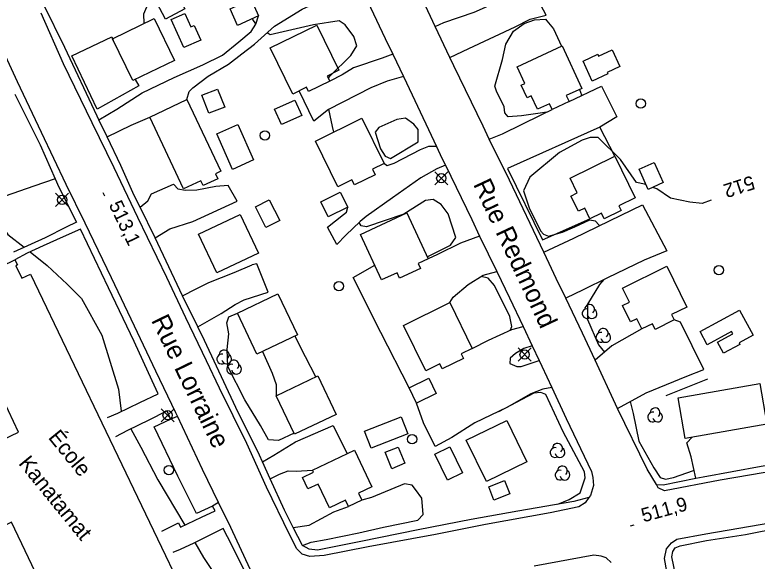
# Model space of a CAD drawing. Extents: x 347312 to 350503, y 6073086 to 6076432.
# Drawn here: x 348862.1 to 349021.2, y 6074615.9 to 6074732.9 of the extents above; entities that cross this region are included whole.
import ezdxf

# ---------------------------------------------------------------- set-up
doc = ezdxf.new("R2010")
doc.units = 0
for name, color, linetype in [('Level 19', 7, 'Continuous'), ('Level 2', 7, 'Continuous'), ('Level 21', 7, 'Continuous'), ('Level 22', 7, 'Continuous'), ('Level 3', 7, 'Continuous'), ('Level 31', 7, 'Continuous'), ('Level 36', 7, 'Continuous'), ('Level 37', 7, 'Continuous'), ('Level 44', 7, 'Continuous')]:
    doc.layers.add(name, color=color, linetype=linetype)

msp = doc.modelspace()

# ---------------------------------------------------------------- linework, layer by layer
at = {"layer": 'Level 19'}
for points in [[(348889.87, 6074731.09), (348889.77, 6074733.14), (348891.41, 6074737.04), (348894.53, 6074740.4), (348897.34, 6074743), (348900.6, 6074744.53), (348903.28, 6074745.57), (348908.05, 6074747.46), (348909.47, 6074746.18)], [(348955.36, 6074723.79), (348955.36, 6074723.79), (348959.47, 6074725.71), (348969.36, 6074730.33), (348972.59, 6074731.98), (348976, 6074732.88), (348974.22, 6074736.25), (348972.65, 6074740.46)], [(348898.99, 6074714.8), (348899.51, 6074716.53), (348900.28, 6074717.32), (348903.57, 6074719.8), (348907.9, 6074722.38), (348910.8, 6074724.6), (348913.53, 6074726.67), (348917.76, 6074730.47), (348923.75, 6074734.15), (348929.07, 6074736.65), (348933.78, 6074738.8), (348935.83, 6074739.83)], [(348952.23, 6074730.46), (348954.07, 6074731.26), (348960.6, 6074733.49), (348966.05, 6074735.9)], [(348880.12, 6074710.46), (348884.02, 6074712.69), (348889.45, 6074716.21), (348896.27, 6074719.53), (348902.39, 6074722.25), (348906.63, 6074724.31), (348910.16, 6074727.13), (348912.78, 6074729.33), (348913.78, 6074730.94), (348914.38, 6074732.74)], [(348943.13, 6074724.49), (348940.83, 6074723.62), (348934.69, 6074721.56), (348932.3, 6074720.08), (348929.65, 6074718.75)], [(348945.43, 6074719.71), (348941.95, 6074718.7), (348938.42, 6074717.32), (348929.38, 6074712.67), (348926.25, 6074710.18), (348923.1, 6074716.64)], [(348980.97, 6074714.37), (348987.91, 6074717.63), (348991.14, 6074711.08), (348987.53, 6074708.87)], [(348963.83, 6074706.32), (348966.68, 6074707.43), (348974.97, 6074711.53), (348977.28, 6074712.65)], [(348881.9, 6074706.76), (348887.09, 6074709.31), (348891.03, 6074711.03)], [(348952.52, 6074704.73), (348950.76, 6074704.69), (348948.98, 6074704.02), (348943.34, 6074701.09), (348941.86, 6074700.57), (348941.28, 6074701.05)], [(348954.42, 6074700.74), (348952.58, 6074699.94), (348949.13, 6074698.01), (348943.09, 6074693.76), (348937.45, 6074689.76), (348936.16, 6074688.68), (348933.07, 6074685.7), (348931.18, 6074683.72), (348929.11, 6074687.45), (348932.55, 6074690.19), (348933.24, 6074690.63), (348933.47, 6074691.72)], [(348870.76, 6074697.79), (348866.2, 6074696.26), (348860.06, 6074694.06), (348857.85, 6074693.33)], [(348888.99, 6074691.71), (348890.6, 6074693.07), (348891.39, 6074694.56), (348896.12, 6074696.63)], [(348892.24, 6074685.13), (348895.33, 6074687.08), (348900.27, 6074688.67), (348909.76, 6074693.02), (348907.83, 6074696.4), (348905.18, 6074696.14), (348901.16, 6074695.34), (348898.61, 6074695.32), (348897.15, 6074695.61), (348896.12, 6074696.63)], [(348975.48, 6074682.12), (348981.91, 6074685.1), (348992.11, 6074690.05), (348996.65, 6074692.21), (349001.89, 6074682.35), (348997.04, 6074680.39), (348989.16, 6074676.63), (348983.93, 6074674.05), (348980.21, 6074672.26)], [(348961.76, 6074685.55), (348957.64, 6074683.99), (348952.75, 6074681.62), (348950.72, 6074680.67)], [(348898.07, 6074672.74), (348900.99, 6074674.24), (348903.73, 6074675.57), (348909.15, 6074677.71), (348913.03, 6074679.39)], [(348901.32, 6074666.13), (348906.35, 6074668.96), (348909.38, 6074670.91), (348911.31, 6074671.86), (348916.46, 6074673.54), (348913.97, 6074679.57), (348913.03, 6074679.39)], [(348946.65, 6074653.02), (348940.58, 6074664.91), (348934.66, 6074676.64), (348939.29, 6074679.29)], [(348955.36, 6074671.28), (348956.11, 6074672.45), (348959.26, 6074675.18), (348962.51, 6074677.16), (348965.43, 6074677.96)], [(348991.31, 6074648.63), (348997.42, 6074651.96), (349006.19, 6074655.56), (349009.84, 6074656.97), (349004.8, 6074667.12), (349003.47, 6074667.58)], [(348960.18, 6074661.47), (348963.66, 6074663.26), (348968.62, 6074665.55), (348971.06, 6074666.19)], [(348996.55, 6074665.65), (348990.08, 6074662.02), (348986.51, 6074658.95)], [(348973.02, 6074662.03), (348971.21, 6074661.49), (348969.43, 6074660.37), (348968.28, 6074659.4), (348968.26, 6074658.25), (348969.73, 6074657.59), (348970.63, 6074657.59), (348974.49, 6074658.91)], [(348977.21, 6074653.13), (348975.32, 6074652.74), (348972.76, 6074651.72), (348967.55, 6074648.85), (348960.76, 6074645.53), (348955.82, 6074642.42), (348952.2, 6074640.44), (348949.75, 6074645.51), (348948.24, 6074649.74)], [(348905.8, 6074628.47), (348904.52, 6074627.66), (348901.07, 6074626.12), (348897.09, 6074634.13), (348891.98, 6074644.69), (348895.49, 6074646.35), (348896.99, 6074646.94)], [(348915.23, 6074637.18), (348917.61, 6074638.62), (348922.27, 6074641.47), (348930.37, 6074644.95), (348933.35, 6074638.92)], [(349008.08, 6074633.66), (349007.08, 6074638.27), (349006.14, 6074641.28), (349007.31, 6074642.44)], [(348916.87, 6074633.55), (348918.87, 6074634.55), (348920.74, 6074635.29), (348922.41, 6074635.22), (348925.92, 6074635.39)], [(348923.79, 6074619.23), (348925.63, 6074619.98), (348928.87, 6074620.52), (348935.89, 6074621.96), (348941.18, 6074623.16), (348948.49, 6074624.7), (348949.62, 6074625.87), (348949.38, 6074629.39), (348948.02, 6074631.27), (348947.28, 6074632.16), (348945.66, 6074632.47), (348938.55, 6074629.51), (348936.47, 6074628.98)], [(348921.8, 6074623.13), (348925.21, 6074623.65), (348930.49, 6074626.44), (348933.64, 6074627.64)]]:
    msp.add_lwpolyline(points, dxfattribs=at)
at = {"layer": 'Level 2'}
for points in [[(348913.79, 6074730.97), (348913.12, 6074731.93), (348913.06, 6074732.14)], [(348965.02, 6074717.62), (348966.66, 6074723.33), (348967.35, 6074726.66), (348968.98, 6074729.4), (348971.3, 6074731.05), (348973.51, 6074731.85), (348975.9, 6074731.97), (348976.17, 6074731.65), (348977.59, 6074729.96), (348979.28, 6074726.22)], [(348929.35, 6074719.34), (348929.67, 6074719.78), (348934.17, 6074724.25), (348935.41, 6074726.29), (348934.76, 6074728.32), (348932.91, 6074730.8), (348931.62, 6074731.61), (348926.16, 6074730.82), (348916.88, 6074728.62), (348916.19, 6074729.06)], [(348976.14, 6074712.1), (348974.23, 6074711.78), (348970.7, 6074711.31), (348967.84, 6074711.11), (348967.17, 6074711.91), (348967.04, 6074713.24), (348965.38, 6074716.56), (348965.02, 6074717.62)], [(348983.15, 6074716.94), (348983.58, 6074715.78), (348983.52, 6074715.57)], [(348930.53, 6074707.83), (348930.25, 6074709), (348929.75, 6074711.4), (348929.44, 6074712.7)], [(348942.65, 6074702.19), (348948.55, 6074705.71), (348948.57, 6074708.39), (348947.68, 6074709.54), (348945.89, 6074710.77), (348943.97, 6074710.53), (348940.16, 6074708.76), (348939.34, 6074707.76), (348940.48, 6074704.24), (348941.54, 6074702.62), (348942.65, 6074702.19)], [(348997.43, 6074696.52), (348997.1, 6074696.65), (348995.36, 6074697), (348991.92, 6074701.92), (348987.14, 6074706.63), (348985.46, 6074706.66), (348983.76, 6074706.06), (348978.85, 6074703.45), (348972.48, 6074698.15), (348971.16, 6074695.22), (348972.38, 6074691.61), (348974.79, 6074686.66), (348975.44, 6074685.98), (348976.51, 6074685.52), (348979.54, 6074686.4), (348982.18, 6074687.49), (348985.35, 6074689.03), (348986.53, 6074688.8), (348987.36, 6074687.9), (348987.46, 6074687.79)], [(349011.37, 6074693.26), (349009.45, 6074692.55), (349006.8, 6074692.82), (349002.69, 6074693.68), (348999.77, 6074695.63), (348998.87, 6074695.97)], [(348950.54, 6074681.06), (348955.5, 6074683.62), (348956.66, 6074685.2), (348955.04, 6074690.29), (348953.52, 6074692.28), (348951.8, 6074693.34), (348950.18, 6074693.19), (348945.49, 6074690.22), (348937.49, 6074687.51), (348936.39, 6074687.73), (348935.92, 6074688.45)], [(348857.03, 6074691.92), (348857.56, 6074690.83), (348858.72, 6074688.72), (348860.64, 6074685.9), (348864.14, 6074683.13)], [(348865.39, 6074682.14), (348869.06, 6074679.23), (348873.36, 6074675.24), (348876.43, 6074672.2), (348880.74, 6074664.29), (348884.36, 6074652.72), (348884.93, 6074648.04), (348884.95, 6074648.01)], [(348968.37, 6074665.43), (348968.66, 6074666.15), (348968.22, 6074668.29), (348964.96, 6074674.96), (348963.57, 6074676.52), (348962.05, 6074676.88)], [(348988.37, 6074676.24), (348987.46, 6074675.16), (348984.85, 6074670.99), (348984.85, 6074667.65), (348987.23, 6074662.21), (348988.55, 6074660.7)], [(348921.97, 6074643.31), (348918.64, 6074641.72), (348916.53, 6074641.92), (348914.76, 6074644.98), (348911.42, 6074650.49), (348907.81, 6074657.6), (348907.64, 6074661.25), (348908.03, 6074664.61), (348907.58, 6074666.96), (348908.02, 6074668.24), (348909.83, 6074669)], [(348915.24, 6074660.85), (348917.27, 6074656.2), (348918.11, 6074653.72), (348918.14, 6074651.35)], [(348978.55, 6074628.12), (348980.96, 6074629.09), (348983.3, 6074630.54), (348984.39, 6074633.73), (348984.21, 6074635.02), (348979.65, 6074643.61), (348975.97, 6074651.59), (348974.9, 6074652.05), (348973.36, 6074651.9), (348965.79, 6074647.87), (348965.75, 6074647.97)], [(348994.05, 6074650.12), (348994.69, 6074647.56), (348995.91, 6074641.61), (348999.12, 6074635.9), (349000.46, 6074633.85)], [(348886.98, 6074644.26), (348889.1, 6074640.34), (348892.77, 6074633.35), (348898.55, 6074623.6)], [(349000.46, 6074633.85), (349001.58, 6074633.5), (349003.33, 6074633.84), (349007.61, 6074635.32), (349007.71, 6074635.34)], [(348900.73, 6074619.88), (348902.59, 6074616.7), (348907.52, 6074609.27), (348908.57, 6074606.82), (348908.49, 6074603.65), (348907.56, 6074596.51), (348907.55, 6074596.27)]]:
    msp.add_lwpolyline(points, dxfattribs=at)
at = {"layer": 'Level 21'}
for points in [[(348976.64, 6074679.7), (348975.48, 6074682.12), (348968.12, 6074697.51), (348963.83, 6074706.32), (348962.48, 6074709.1), (348956.2, 6074721.99), (348955.36, 6074723.79), (348952.23, 6074730.46), (348949.68, 6074735.9), (348944.97, 6074745.62), (348943.05, 6074749.58), (348942.14, 6074751.46), (348936.66, 6074762.79), (348935.57, 6074764.98), (348932.5, 6074771.18), (348931.17, 6074773.85), (348923.43, 6074790.67), (348914.53, 6074809.33), (348908.74, 6074821.47)], [(348935.83, 6074739.83), (348941.52, 6074727.84), (348943.13, 6074724.49), (348945.43, 6074719.71), (348947.3, 6074715.82), (348952.52, 6074704.73), (348953.68, 6074702.26), (348954.42, 6074700.74), (348960.06, 6074689.08), (348961.76, 6074685.55), (348965.43, 6074677.96), (348968.18, 6074672.29), (348971.06, 6074666.19), (348973.02, 6074662.03), (348974.49, 6074658.91), (348975.08, 6074657.68), (348977.21, 6074653.13), (348980.33, 6074646.47), (348985.73, 6074635.09), (348986.04, 6074633.83), (348986.18, 6074632.13), (348985.55, 6074630), (348985.18, 6074629.51)], [(348985.18, 6074629.51), (348984.38, 6074628.42), (348983, 6074627.55), (348976.85, 6074626.24), (348963, 6074623.75), (348952.31, 6074621.64), (348937.84, 6074619), (348928.44, 6074617.15), (348925.39, 6074616.92), (348923.74, 6074617.43), (348922.57, 6074618.56), (348920.98, 6074621.62), (348916.08, 6074631.75), (348911.86, 6074641.08), (348906.03, 6074652.94), (348903.2, 6074658.83), (348898.76, 6074668.06), (348894.71, 6074676.65), (348888.47, 6074689.55), (348883.4, 6074700.18), (348878.73, 6074709.78), (348872.58, 6074722.4), (348867.8, 6074733.25)], [(348912.56, 6074614.21), (348908.42, 6074623.14), (348905.8, 6074628.47), (348902.33, 6074635.52), (348896.99, 6074646.94), (348896.63, 6074647.71), (348892.32, 6074656.6), (348887.75, 6074666.26), (348882.85, 6074676.57), (348877.17, 6074688.27), (348873.14, 6074696.57), (348867.85, 6074707.71), (348862.67, 6074718.56), (348857.88, 6074728.75)], [(349028.79, 6074635.92), (349013.28, 6074633.25), (349001.35, 6074631), (349000.05, 6074631.65), (348999.63, 6074632.34), (348997.63, 6074635.61), (348991.31, 6074648.63), (348990.87, 6074649.57), (348986.51, 6074658.95), (348983.8, 6074664.77), (348980.21, 6074672.26), (348978.19, 6074676.48), (348976.64, 6074679.7)], [(349003.17, 6074606.57), (349001.4, 6074616.51), (349001.81, 6074618.53), (349002.87, 6074619.87), (349004, 6074620.6), (349010.22, 6074621.74), (349024.39, 6074624.2), (349034.18, 6074625.94), (349046.52, 6074628.23), (349057.62, 6074630.38), (349061.26, 6074630.64), (349061.26, 6074630.64), (349076.97, 6074633.95), (349079.05, 6074634.34), (349093.69, 6074637.13), (349111.47, 6074640.3), (349123.49, 6074642.7), (349133.45, 6074644.58)], [(348989.97, 6074615.59), (348988.9, 6074616.59), (348987.83, 6074616.97), (348986.2, 6074617.2), (348973.44, 6074614.86)]]:
    msp.add_lwpolyline(points, dxfattribs=at)
at = {"layer": 'Level 22'}
for points in [[(348985.18, 6074629.51), (348981.91, 6074628.7), (348969.91, 6074626.63), (348959.94, 6074624.83), (348948.59, 6074622.61), (348936.31, 6074620.15), (348927, 6074618.29), (348925.25, 6074618.49), (348923.79, 6074619.23), (348921.8, 6074623.13), (348919.91, 6074626.8), (348916.87, 6074633.55), (348915.23, 6074637.18), (348914.58, 6074638.61), (348909.53, 6074648.84), (348902.77, 6074663.17), (348901.32, 6074666.13), (348898.07, 6074672.74), (348897.47, 6074673.97), (348892.24, 6074685.13), (348888.99, 6074691.71), (348887.74, 6074694.26), (348884.86, 6074700.65), (348881.9, 6074706.76), (348880.12, 6074710.46), (348879.74, 6074711.24), (348872.82, 6074725.95), (348868.31, 6074735.09)], [(348862.1, 6074715.97), (348867.53, 6074705.11), (348870.76, 6074697.79), (348871.55, 6074696.02), (348875.38, 6074688.51), (348873.15, 6074687.45), (348868.6, 6074685.13), (348861.86, 6074682.11)], [(348999.63, 6074632.34), (349001.1, 6074632.29), (349008.08, 6074633.66), (349009.66, 6074633.97), (349022.09, 6074636.25), (349024.64, 6074636.66), (349030.29, 6074637.55), (349038.57, 6074639.3), (349042.69, 6074639.96), (349047.62, 6074641.01), (349056, 6074642.46), (349057.78, 6074643.58), (349058.26, 6074644.44), (349058.76, 6074645.92), (349058.81, 6074647.48), (349056.3, 6074655.06), (349053.4, 6074663.3), (349052.31, 6074666.09), (349051.25, 6074668.84), (349047.78, 6074677.17), (349047.54, 6074677.77), (349043.16, 6074686.6), (349038.83, 6074695.01), (349040.24, 6074695.56)], [(348881.96, 6074646.69), (348884.17, 6074647.64), (348888.91, 6074649.88), (348892.88, 6074651.78), (348891.55, 6074654.53), (348887.7, 6074662.98), (348882.2, 6074674.45), (348876.18, 6074687), (348872.47, 6074685.39), (348868.23, 6074683.42), (348864.77, 6074681.87), (348862.16, 6074680.43)], [(348883.8, 6074642.63), (348886.37, 6074643.96), (348890.9, 6074646.18), (348894.68, 6074648.14), (348895.49, 6074646.35)], [(349004.28, 6074610.3), (349002.92, 6074616.87), (349003.18, 6074618), (349003.65, 6074618.78), (349004.72, 6074619.22), (349010.35, 6074620.33), (349018.71, 6074621.62), (349034.24, 6074624.7), (349044.78, 6074626.53), (349057.42, 6074628.92), (349061.6, 6074629.33), (349062.52, 6074628.68), (349062.93, 6074627.2), (349064.58, 6074627.31)], [(348893.65, 6074622.34), (348897.2, 6074624.11), (348897.66, 6074623.18), (348902.11, 6074625.32), (348905.04, 6074626.66), (348904.52, 6074627.66)], [(348891.79, 6074597), (348897.96, 6074594.77), (348908.57, 6074596.43), (348916.04, 6074597.8), (348915.4, 6074602.02), (348914.05, 6074607.02), (348912.11, 6074612.28), (348908.62, 6074619.33), (348906.78, 6074622.93), (348900.48, 6074619.76), (348897.55, 6074618.42), (348896.01, 6074617.74)]]:
    msp.add_lwpolyline(points, dxfattribs=at)
at = {"layer": 'Level 3'}
for p, q in [((348881, 6074694.87), (348881.35, 6074694.15)), ((348994.08, 6074623.46), (348994.85, 6074623.68))]:
    msp.add_line(p, q, dxfattribs=at)
at = {"layer": 'Level 31'}
for points in [[(348892.55, 6074735.52), (348896.72, 6074737.75), (348898.6, 6074734.21), (348894.43, 6074731.98), (348892.55, 6074735.52)], [(348908.25, 6074734.18), (348912.78, 6074736.25), (348914.38, 6074732.74), (348909.85, 6074730.67), (348908.25, 6074734.18)], [(348891.99, 6074732.12), (348896.33, 6074723.18), (348887.4, 6074718.85), (348883.06, 6074727.79), (348891.99, 6074732.12)], [(348899.85, 6074730.33), (348900.59, 6074730.66), (348901.98, 6074727.53), (348898.35, 6074725.91), (348895.67, 6074731.93), (348898.57, 6074733.21), (348899.85, 6074730.33)], [(348929.65, 6074718.75), (348925.09, 6074716.52), (348924.66, 6074717.4), (348921.71, 6074715.96), (348916.88, 6074725.85), (348926.86, 6074730.72), (348931.59, 6074721.04), (348929.1, 6074719.82), (348929.65, 6074718.75)], [(348980.97, 6074714.37), (348977.28, 6074712.65), (348976.71, 6074713.87), (348974.16, 6074712.69), (348972.83, 6074715.55), (348971.92, 6074715.13), (348970.65, 6074717.86), (348971.45, 6074718.23), (348969.78, 6074721.82), (348979.44, 6074726.3), (348983.67, 6074717.18), (348980.3, 6074715.62), (348980.97, 6074714.37)], [(348985.89, 6074718.74), (348983.92, 6074722.99), (348987.08, 6074724.47), (348987.26, 6074724.08), (348990.16, 6074725.43), (348991.83, 6074721.83), (348989.1, 6074720.56), (348989.23, 6074720.29), (348985.89, 6074718.74)], [(348905.59, 6074717.03), (348907.11, 6074713.16), (348903.74, 6074711.83), (348902.22, 6074715.71), (348905.59, 6074717.03)], [(348906.26, 6074699.43), (348905.13, 6074698.89), (348905.64, 6074697.8), (348902.47, 6074696.36), (348901.97, 6074697.4), (348898.3, 6074695.66), (348891.03, 6074711.03), (348898.99, 6074714.8), (348906.26, 6074699.43)], [(348917.82, 6074712.71), (348922.14, 6074714.67), (348923.63, 6074711.4), (348919.32, 6074709.43), (348917.82, 6074712.71)], [(348931.35, 6074696.12), (348926.55, 6074705.87), (348936.5, 6074710.76), (348941.28, 6074701.05), (348938.82, 6074699.84), (348939.39, 6074698.67), (348934.94, 6074696.48), (348934.38, 6074697.61), (348931.35, 6074696.12)], [(348909.92, 6074709.46), (348913.3, 6074701.84), (348908.78, 6074699.83), (348905.4, 6074707.45), (348909.92, 6074709.46)], [(348992.12, 6074691.04), (348988.45, 6074689.25), (348987.86, 6074690.46), (348985.39, 6074689.25), (348984.28, 6074691.52), (348982.91, 6074690.85), (348981.32, 6074694.11), (348982.68, 6074694.78), (348981.13, 6074697.95), (348990.75, 6074702.65), (348995.11, 6074693.75), (348991.59, 6074692.02), (348992.12, 6074691.04)], [(348999.15, 6074701.32), (349001.12, 6074696.99), (348997.89, 6074695.52), (348995.92, 6074699.85), (348999.15, 6074701.32)], [(348933.47, 6074691.72), (348929.31, 6074689.66), (348927.71, 6074692.9), (348931.86, 6074694.96), (348933.47, 6074691.72)], [(348916.65, 6074693.32), (348918.9, 6074688.85), (348915.93, 6074687.36), (348913.68, 6074691.83), (348916.65, 6074693.32)], [(348910.39, 6074690.18), (348914.33, 6074681.9), (348905.4, 6074677.66), (348901.47, 6074685.93), (348910.39, 6074690.18)], [(348940.73, 6074676.15), (348936.23, 6074685.91), (348946.18, 6074690.51), (348950.72, 6074680.67), (348948.58, 6074679.68), (348949.08, 6074678.61), (348944.58, 6074676.54), (348944.05, 6074677.68), (348940.73, 6074676.15)], [(348848.4, 6074673.84), (348862.16, 6074680.43), (348862.67, 6074679.36), (348862.32, 6074679.19), (348863.61, 6074676.49), (348865.52, 6074677.41), (348899.47, 6074606.52)], [(349003.47, 6074667.58), (348999.39, 6074665.56), (348998.8, 6074666.76), (348996.55, 6074665.65), (348995.47, 6074667.84), (348994.08, 6074667.16), (348992.35, 6074670.65), (348993.85, 6074671.39), (348992.38, 6074674.37), (349001.89, 6074679.06), (349006.18, 6074670.34), (349002.88, 6074668.71), (349003.47, 6074667.58)], [(348918.51, 6074673.16), (348922.7, 6074664.42), (348914.01, 6074660.26), (348909.83, 6074669), (348918.51, 6074673.16)], [(348950.19, 6074656.65), (348945.4, 6074666.39), (348955.36, 6074671.28), (348960.18, 6074661.47), (348957.83, 6074660.31), (348958.32, 6074659.32), (348953.75, 6074657.07), (348953.22, 6074658.14), (348950.19, 6074656.65)], [(349017.48, 6074669.67), (349020.38, 6074664.32), (349017.38, 6074662.69), (349017.56, 6074662.35), (349014.03, 6074660.43), (349012.73, 6074662.82), (349015.99, 6074664.59), (349015.72, 6074665.07), (349010.54, 6074662.26), (349009.01, 6074665.07), (349017.48, 6074669.67)], [(348922.07, 6074643.08), (348918.14, 6074651.35), (348927.05, 6074655.59), (348930.98, 6074647.33), (348922.07, 6074643.08)], [(348950.88, 6074655.07), (348952.47, 6074651.79), (348948.24, 6074649.74), (348946.65, 6074653.02), (348950.88, 6074655.07)], [(349004.28, 6074650.87), (349021.79, 6074653.98), (349023.34, 6074645.28), (349005.82, 6074642.17), (349004.28, 6074650.87)], [(348854.23, 6074639.4), (348862.91, 6074643.55), (348858.54, 6074652.68)], [(348944.93, 6074646.8), (348946.35, 6074643.15), (348938.51, 6074640.1), (348937.09, 6074643.75), (348944.93, 6074646.8)], [(348967.61, 6074646.06), (348971.89, 6074637.19), (348963.19, 6074632.98), (348958.9, 6074641.85), (348967.61, 6074646.06)], [(348934.9, 6074639.66), (348938.62, 6074631.83), (348935.76, 6074630.47), (348936.47, 6074628.98), (348933.64, 6074627.64), (348933, 6074629), (348929.55, 6074627.36), (348927.14, 6074632.41), (348924.95, 6074631.37), (348923.78, 6074633.83), (348926.13, 6074634.95), (348925.92, 6074635.39), (348934.9, 6074639.66)], [(348944.28, 6074640.36), (348945.7, 6074636.87), (348942.9, 6074635.72), (348941.47, 6074639.22), (348944.28, 6074640.36)], [(348954.86, 6074633.29), (348952.17, 6074638.82), (348955.39, 6074640.38), (348958.08, 6074634.85), (348954.86, 6074633.29)], [(348968.21, 6074630.32), (348964.82, 6074628.97), (348963.69, 6074631.81), (348967.08, 6074633.16), (348968.21, 6074630.32)], [(348868.01, 6074610.47), (348861.41, 6074624.25), (348848.82, 6074618.22), (348849.4, 6074617), (348846.49, 6074615.61), (348845.84, 6074616.98), (348831.86, 6074610.28)]]:
    msp.add_lwpolyline(points, dxfattribs=at)
at = {"layer": 'Level 36'}
for p, q in [((348952.13, 6074696.51), (348954.95, 6074699.33)), ((348952.13, 6074699.33), (348954.95, 6074696.51)), ((348870.84, 6074691.89), (348873.66, 6074694.71)), ((348870.84, 6074694.71), (348873.66, 6074691.89)), ((348969.99, 6074658.76), (348972.81, 6074661.58)), ((348969.99, 6074661.58), (348972.81, 6074658.76)), ((348893.47, 6074645.75), (348896.29, 6074648.57)), ((348893.47, 6074648.57), (348896.29, 6074645.75))]:
    msp.add_line(p, q, dxfattribs=at)
for centre in [(348996.29, 6074713.93), (348915.72, 6074707.1), (348953.54, 6074697.92), (348872.25, 6074693.3), (349013.05, 6074678.24), (348931.58, 6074674.81), (348971.4, 6074660.17), (348894.88, 6074647.16), (348947.27, 6074642.03), (348895.15, 6074635.41)]:
    msp.add_circle(centre, 1, dxfattribs=at)
at = {"layer": 'Level 37'}
for points in [[(348887.9, 6074719.09), (348888.7, 6074717.72), (348879.77, 6074712.7), (348874.33, 6074724.18), (348882.89, 6074728.21), (348883.23, 6074727.43)], [(348990.75, 6074702.65), (348987.53, 6074708.87), (348967.71, 6074699.99), (348975.25, 6074684.7), (348985.39, 6074689.25)], [(348926.61, 6074655.38), (348924.43, 6074659.64), (348922.17, 6074664.16)], [(349001.75, 6074651.36), (349010.67, 6074654.94)]]:
    msp.add_lwpolyline(points, dxfattribs=at)
at = {"layer": 'Level 44'}
for centre, start, end in [((348984.8, 6074668.94), 76.8848, 299.5691), ((348985.32, 6074669.84), 314.0633, 179.7519), ((348985.85, 6074668.94), 192.2171, 59.6742), ((348988.25, 6074664.73), 314.0633, 179.7519), ((348987.73, 6074663.83), 76.8848, 299.5691), ((348988.78, 6074663.83), 192.2171, 59.6742), ((348907, 6074660.09), 314.0633, 179.7519), ((348906.48, 6074659.19), 76.8848, 299.5691), ((348907.53, 6074659.19), 192.2171, 59.6742), ((348909.11, 6074657.93), 314.0633, 179.7519), ((348908.59, 6074657.03), 76.8848, 299.5691), ((348909.64, 6074657.03), 192.2171, 59.6742), ((348998.85, 6074646.78), 76.8848, 299.5691), ((348999.37, 6074647.68), 314.0633, 179.7519), ((348999.9, 6074646.78), 192.2171, 59.6742), ((348977.93, 6074639.18), 76.8848, 299.5691), ((348978.45, 6074640.08), 314.0633, 179.7519), ((348978.98, 6074639.18), 192.2171, 59.6742), ((348978.99, 6074634.34), 76.8848, 299.5691), ((348979.51, 6074635.24), 314.0633, 179.7519), ((348980.04, 6074634.34), 192.2171, 59.6742)]:
    msp.add_arc(centre, 1.05, start, end, dxfattribs=at)

# ---------------------------------------------------------------- texts
at = {"layer": 'Level 2'}
msp.add_text('512', height=3, rotation=197.8407, dxfattribs=at).set_placement((349020.12, 6074698.55))
at = {"layer": 'Level 21'}
for s, rotation, p in [('Rue Redmond', 295.0909, (348960.31, 6074696.66)), ('Rue Lorraine', 295.871, (348891.28, 6074667.52))]:
    msp.add_text(s, height=4, rotation=rotation, dxfattribs=at).set_placement(p)
at = {"layer": 'Level 3'}
for s, rotation, p in [('513,1', 295.5493, (348882.21, 6074692.26)), ('511,9', 15.4001, (348996.87, 6074624.2))]:
    msp.add_text(s, height=3, rotation=rotation, dxfattribs=at).set_placement(p)
at = {"layer": 'Level 31'}
for s, p in [('École', (348869.14, 6074642.35)), ('Kanatamat', (348862.77, 6074636.8))]:
    msp.add_text(s, height=3.33, rotation=309.1656, dxfattribs=at).set_placement(p)

doc.saveas('drawing.dxf')
